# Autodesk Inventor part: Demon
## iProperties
Shininess: 64.0
Length Units: 11269
Angle Units: 11279
Time Units: 11290
Mass Units: 11283
Length Display Precision: 3
Angle Display Precision: 2
Compacted: True
Part Number: Demon
Document SubType Name: Modeling
Created: 2005-04
Material: Steel, Mild
Designer: John Blackburn
Manufacturer: Standard
Standards Organization: Custom
Density: 0.0
Volumn: 0.0
Area: 0.0
PropertySet Name: Model Information
Control State: 0
Master: False
Checked Out: False
Author: John Blackburn
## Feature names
1. Extrusion1
2. Extrusion2
